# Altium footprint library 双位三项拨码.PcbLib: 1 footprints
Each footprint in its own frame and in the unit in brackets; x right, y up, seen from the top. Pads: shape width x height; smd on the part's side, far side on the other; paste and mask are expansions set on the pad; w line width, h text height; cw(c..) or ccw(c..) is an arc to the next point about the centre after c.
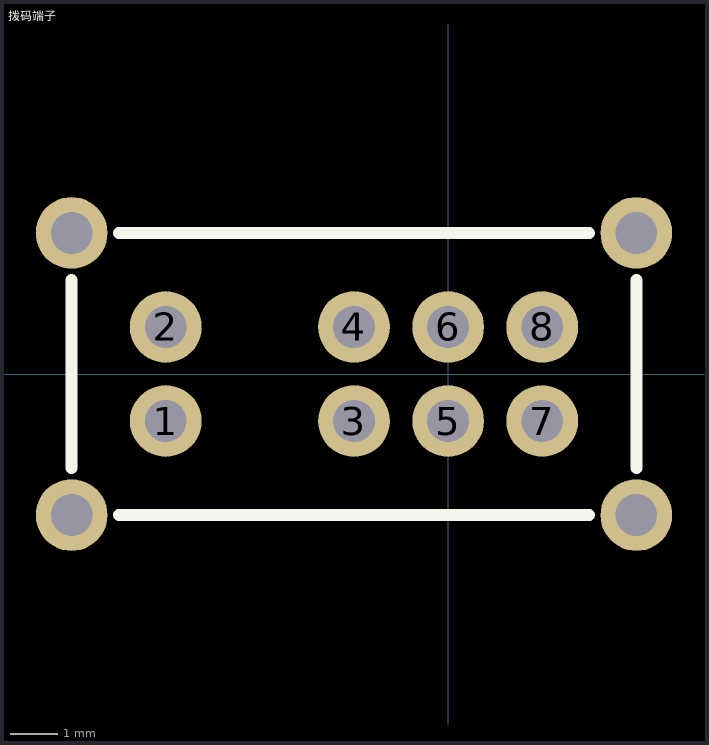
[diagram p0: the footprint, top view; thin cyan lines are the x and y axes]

## 拨码端子 [mil] "拨码端子"
pads (12):
  round 60 hole 35: 1(-236.22,-39.37) 2(-236.22,39.37) 3(-78.74,-39.37) 4(-78.74,39.37) 5(0,-39.37) 6(0,39.37) 7(78.74,-39.37) 8(78.74,39.37) ""(-314.96,-118.11) ""(-314.96,118.11) ""(157.48,-118.11) ""(157.48,118.11)
Top Overlay:
  lines w10: -314.96,-78.74 -314.96,78.74 ; -275.59,-118.11 118.11,-118.11 ; -275.59,118.11 118.11,118.11 ; 157.48,-78.74 157.48,78.74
